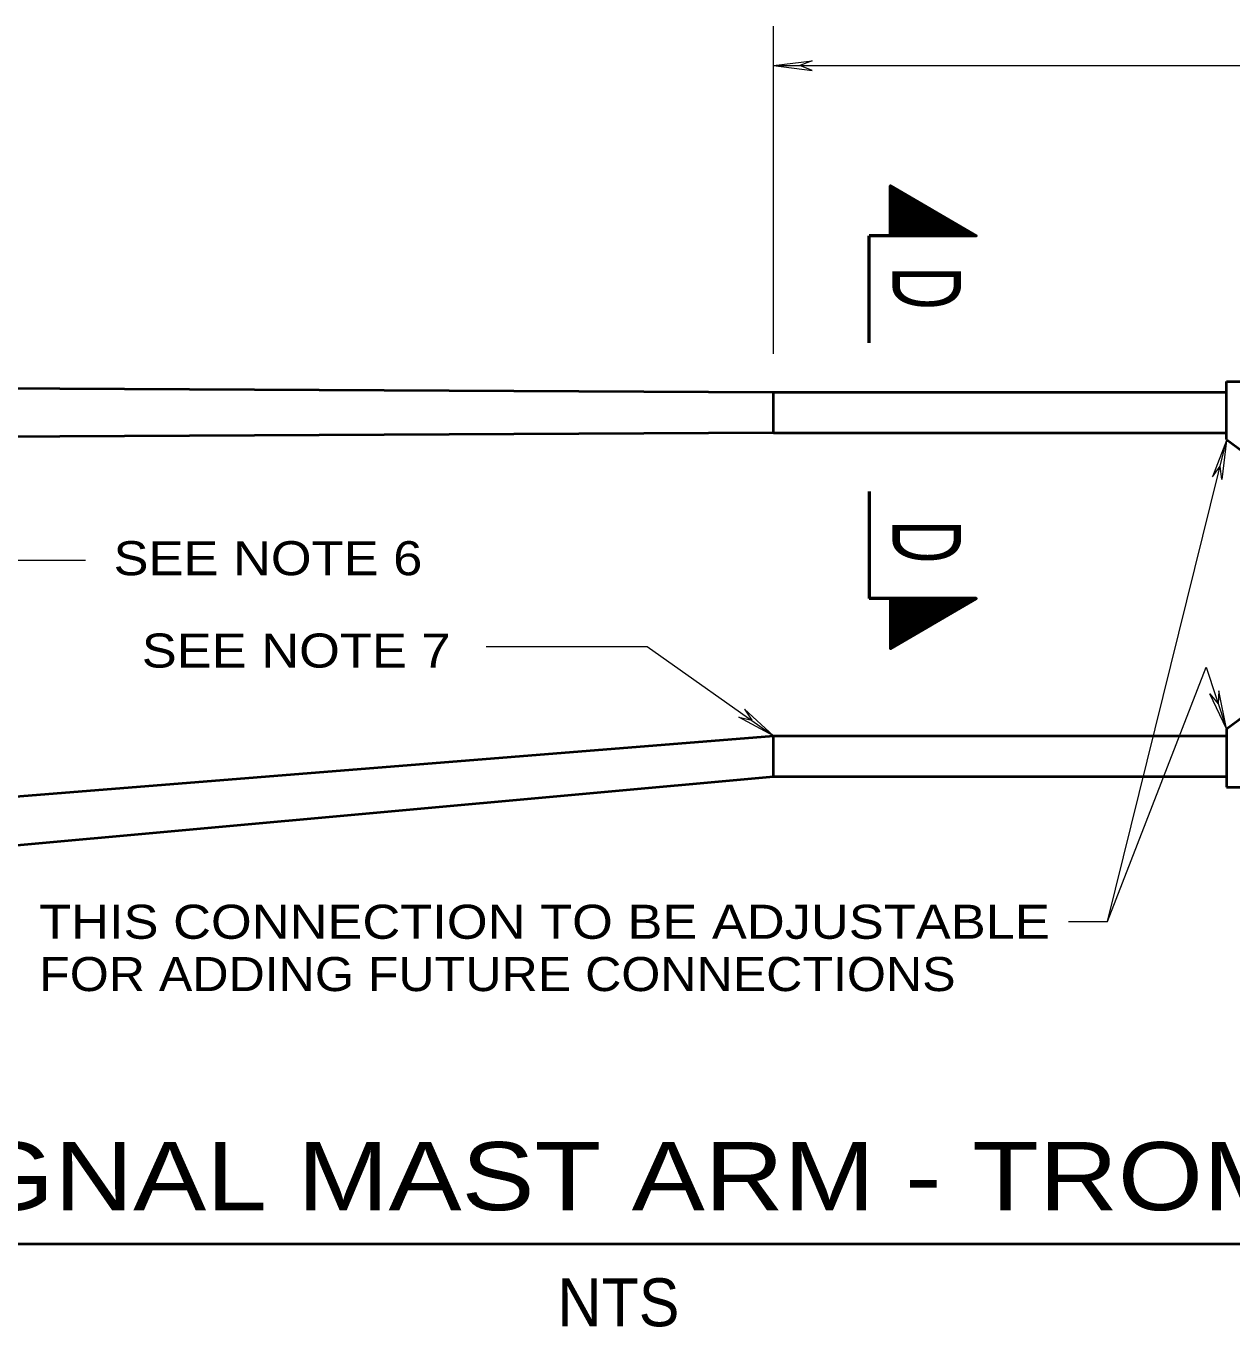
# Model space of a CAD drawing. Extents: x 312583 to 312854, y 144419 to 144597.
# Drawn here: x 312774.43 to 312801.32, y 144536.56 to 144565.58 of the extents above; entities that cross this region are included whole.
import ezdxf
from ezdxf.enums import TextEntityAlignment as Align

# ---------------------------------------------------------------- set-up
doc = ezdxf.new("R2010")
doc.units = 0
doc.header["$LTSCALE"] = 0.3
doc.layers.add('1', color=7, linetype='Continuous', lineweight=35)
doc.layers.add('2', color=7, linetype='Continuous', lineweight=13)

msp = doc.modelspace()

# ---------------------------------------------------------------- linework, layer by layer
at = {"layer": '1'}
for p, q in [((312793.7022, 144561.9803), (312793.7176, 144561.9956)), ((312793.7022, 144561.9343), (312793.7406, 144561.9879)), ((312793.7022, 144561.8806), (312793.7559, 144561.9726)), ((312793.7022, 144561.8346), (312793.7789, 144561.9573)), ((312793.7022, 144561.7809), (312793.8019, 144561.9496)), ((312793.7022, 144561.7426), (312793.8172, 144561.9343)), ((312793.7022, 144561.6889), (312793.8402, 144561.9266)), ((312793.7022, 144561.6429), (312793.8632, 144561.9113)), ((312793.7022, 144561.5969), (312793.8786, 144561.9036)), ((312793.7022, 144561.5509), (312793.9092, 144561.8883)), ((312793.7022, 144561.4973), (312793.9246, 144561.8806)), ((312793.7022, 144561.4513), (312793.9476, 144561.8653)), ((312793.7022, 144561.4053), (312793.9706, 144561.8576)), ((312793.7022, 144561.3516), (312793.9859, 144561.8423)), ((312793.7022, 144561.3056), (312794.0089, 144561.8346)), ((312793.7022, 144561.2596), (312794.0242, 144561.8193)), ((312793.7022, 144561.2059), (312794.0472, 144561.8039)), ((312793.7022, 144561.1599), (312794.0702, 144561.7963)), ((312793.7022, 144561.1139), (312794.0856, 144561.7809)), ((312793.7022, 144561.0679), (312794.1086, 144561.7656)), ((312793.7022, 144561.0143), (312794.1316, 144561.7579)), ((312793.7022, 144560.9759), (312794.1469, 144561.7426)), ((312793.7022, 144560.9223), (312794.1776, 144561.7349)), ((312793.7176, 144560.8993), (312794.1929, 144561.7196)), ((312793.7482, 144560.8993), (312794.2159, 144561.7119)), ((312793.7789, 144560.8993), (312794.2389, 144561.6966)), ((312793.8019, 144560.8993), (312794.2542, 144561.6889)), ((312793.8326, 144560.8993), (312794.2772, 144561.6736)), ((312793.8556, 144560.9069), (312794.3002, 144561.6659)), ((312793.8862, 144560.9069), (312794.3156, 144561.6506)), ((312793.9092, 144560.8993), (312794.3386, 144561.6429)), ((312793.9399, 144560.8993), (312794.3616, 144561.6276)), ((312793.9706, 144560.8993), (312794.3769, 144561.6123)), ((312793.9936, 144560.8993), (312794.3999, 144561.6046)), ((312794.0242, 144560.8993), (312794.4229, 144561.5893)), ((312794.0549, 144560.8993), (312794.4459, 144561.5739)), ((312794.0779, 144560.8993), (312794.4612, 144561.5663)), ((312794.1086, 144560.9069), (312794.4842, 144561.5509)), ((312794.1392, 144560.8993), (312794.5072, 144561.5433)), ((312794.1622, 144560.8993), (312794.5226, 144561.5279)), ((312794.1852, 144560.8993), (312794.5456, 144561.5203)), ((312794.2159, 144560.8993), (312794.5686, 144561.5049)), ((312794.2466, 144560.8993), (312794.5839, 144561.4973)), ((312794.2772, 144560.8993), (312794.6069, 144561.4819)), ((312794.3002, 144560.8993), (312794.6299, 144561.4743)), ((312794.3309, 144560.8993), (312794.6452, 144561.4589)), ((312794.3539, 144560.9069), (312794.6759, 144561.4513)), ((312794.3846, 144560.8993), (312794.6912, 144561.4359)), ((312794.4076, 144560.8993), (312794.7142, 144561.4206)), ((312794.4382, 144560.8993), (312794.7372, 144561.4129)), ((312794.4689, 144560.8993), (312794.7526, 144561.3976)), ((312794.4919, 144560.8993), (312794.7756, 144561.3899)), ((312794.5226, 144560.8993), (312794.7986, 144561.3746)), ((312794.5532, 144560.8993), (312794.8139, 144561.3669)), ((312794.5762, 144560.8993), (312794.8369, 144561.3516)), ((312794.6069, 144560.8993), (312794.8599, 144561.3439)), ((312794.6376, 144560.8993), (312794.8752, 144561.3286)), ((312794.6606, 144560.8993), (312794.8982, 144561.3209)), ((312794.6836, 144560.8993), (312794.9212, 144561.3056)), ((312794.7142, 144560.8993), (312794.9442, 144561.2979)), ((312794.7449, 144560.8993), (312794.9596, 144561.2826)), ((312794.7756, 144560.8993), (312794.9826, 144561.2673)), ((312794.7986, 144560.8993), (312795.0056, 144561.2596)), ((312794.8292, 144560.8993), (312795.0209, 144561.2443)), ((312794.8522, 144560.8993), (312795.0439, 144561.2289)), ((312794.8829, 144560.8993), (312795.0669, 144561.2213)), ((312794.9059, 144560.8993), (312795.0822, 144561.2059)), ((312794.9366, 144560.8993), (312795.1052, 144561.1983)), ((312794.9672, 144560.8993), (312795.1282, 144561.1829)), ((312794.9902, 144560.8993), (312795.1436, 144561.1753)), ((312795.0209, 144560.8993), (312795.1742, 144561.1599)), ((312795.0439, 144560.8993), (312795.1896, 144561.1523)), ((312795.0746, 144560.8993), (312795.2126, 144561.1369)), ((312795.1052, 144560.8993), (312795.2356, 144561.1293)), ((312795.1282, 144560.8993), (312795.2509, 144561.1139)), ((312795.1589, 144560.8993), (312795.2739, 144561.1063)), ((312795.1819, 144560.8993), (312795.2969, 144561.0909)), ((312795.2126, 144560.8993), (312795.3122, 144561.0756)), ((312795.2432, 144560.8993), (312795.3352, 144561.0679)), ((312795.2739, 144560.8993), (312795.3582, 144561.0526)), ((312795.2969, 144560.8993), (312795.3736, 144561.0373)), ((312795.3276, 144560.8993), (312795.3966, 144561.0296)), ((312795.3506, 144560.8993), (312795.4196, 144561.0143)), ((312795.3736, 144560.8993), (312795.4426, 144561.0066)), ((312795.4042, 144560.8993), (312795.4579, 144560.9913)), ((312795.4349, 144560.8993), (312795.4809, 144560.9836)), ((312795.4656, 144560.8993), (312795.5039, 144560.9683)), ((312795.4886, 144560.8993), (312795.5192, 144560.9606)), ((312795.5192, 144560.8993), (312795.5422, 144560.9453)), ((312795.5422, 144560.8993), (312795.5652, 144560.9376)), ((312795.5729, 144560.8993), (312795.5806, 144560.9223)), ((312795.6036, 144560.8993), (312795.6036, 144560.9146)), ((312793.7022, 144552.7803), (312794.1776, 144551.9676)), ((312793.7022, 144552.7266), (312794.1469, 144551.9599)), ((312793.7022, 144552.6883), (312794.1316, 144551.9446)), ((312793.7176, 144552.8033), (312794.1929, 144551.9829)), ((312793.7482, 144552.8033), (312794.2159, 144551.9906)), ((312793.7789, 144552.8033), (312794.2389, 144552.0059)), ((312793.8019, 144552.8033), (312794.2542, 144552.0136)), ((312793.8326, 144552.8033), (312794.2772, 144552.0289)), ((312793.8556, 144552.7956), (312794.3002, 144552.0366)), ((312793.8862, 144552.7956), (312794.3156, 144552.0519)), ((312793.9092, 144552.8033), (312794.3386, 144552.0596)), ((312793.9399, 144552.8033), (312794.3616, 144552.0749)), ((312793.9706, 144552.8033), (312794.3769, 144552.0903)), ((312793.9936, 144552.8033), (312794.3999, 144552.0979)), ((312794.0242, 144552.8033), (312794.4229, 144552.1133)), ((312794.0549, 144552.8033), (312794.4459, 144552.1286)), ((312794.0779, 144552.8033), (312794.4612, 144552.1363)), ((312794.1086, 144552.7956), (312794.4842, 144552.1516)), ((312794.1392, 144552.8033), (312794.5072, 144552.1593)), ((312794.1622, 144552.8033), (312794.5226, 144552.1746)), ((312794.1852, 144552.8033), (312794.5456, 144552.1823)), ((312794.2159, 144552.8033), (312794.5686, 144552.1976)), ((312794.2466, 144552.8033), (312794.5839, 144552.2053)), ((312794.2772, 144552.8033), (312794.6069, 144552.2206)), ((312794.3002, 144552.8033), (312794.6299, 144552.2283)), ((312794.3309, 144552.8033), (312794.6452, 144552.2436)), ((312794.3539, 144552.7956), (312794.6759, 144552.2513)), ((312794.3846, 144552.8033), (312794.6912, 144552.2666)), ((312794.4076, 144552.8033), (312794.7142, 144552.2819)), ((312794.4382, 144552.8033), (312794.7372, 144552.2896)), ((312794.4689, 144552.8033), (312794.7526, 144552.3049)), ((312794.4919, 144552.8033), (312794.7756, 144552.3126)), ((312794.5226, 144552.8033), (312794.7986, 144552.3279)), ((312794.5532, 144552.8033), (312794.8139, 144552.3356)), ((312794.5762, 144552.8033), (312794.8369, 144552.3509)), ((312794.6069, 144552.8033), (312794.8599, 144552.3586)), ((312794.6376, 144552.8033), (312794.8752, 144552.3739)), ((312794.6606, 144552.8033), (312794.8982, 144552.3816)), ((312794.6836, 144552.8033), (312794.9212, 144552.3969)), ((312794.7142, 144552.8033), (312794.9442, 144552.4046)), ((312794.7449, 144552.8033), (312794.9596, 144552.4199)), ((312794.7756, 144552.8033), (312794.9826, 144552.4353)), ((312794.7986, 144552.8033), (312795.0056, 144552.4429)), ((312794.8292, 144552.8033), (312795.0209, 144552.4583)), ((312794.8522, 144552.8033), (312795.0439, 144552.4736)), ((312794.8829, 144552.8033), (312795.0669, 144552.4813)), ((312794.9059, 144552.8033), (312795.0822, 144552.4966)), ((312794.9366, 144552.8033), (312795.1052, 144552.5043)), ((312794.9672, 144552.8033), (312795.1282, 144552.5196)), ((312794.9902, 144552.8033), (312795.1436, 144552.5273)), ((312795.0209, 144552.8033), (312795.1742, 144552.5426)), ((312795.0439, 144552.8033), (312795.1896, 144552.5503)), ((312795.0746, 144552.8033), (312795.2126, 144552.5656)), ((312795.1052, 144552.8033), (312795.2356, 144552.5733)), ((312795.1282, 144552.8033), (312795.2509, 144552.5886)), ((312795.1589, 144552.8033), (312795.2739, 144552.5963)), ((312795.1819, 144552.8033), (312795.2969, 144552.6116)), ((312795.2126, 144552.8033), (312795.3122, 144552.6269)), ((312795.2432, 144552.8033), (312795.3352, 144552.6346)), ((312795.2739, 144552.8033), (312795.3582, 144552.6499)), ((312795.2969, 144552.8033), (312795.3736, 144552.6653)), ((312795.3276, 144552.8033), (312795.3966, 144552.6729)), ((312795.3506, 144552.8033), (312795.4196, 144552.6883)), ((312795.3736, 144552.8033), (312795.4426, 144552.6959)), ((312795.4042, 144552.8033), (312795.4579, 144552.7113)), ((312795.4349, 144552.8033), (312795.4809, 144552.7189)), ((312795.4656, 144552.8033), (312795.5039, 144552.7343)), ((312795.4886, 144552.8033), (312795.5192, 144552.7419)), ((312795.5192, 144552.8033), (312795.5422, 144552.7573)), ((312795.5422, 144552.8033), (312795.5652, 144552.7649)), ((312795.5729, 144552.8033), (312795.5806, 144552.7803)), ((312795.6036, 144552.8033), (312795.6036, 144552.7879)), ((312793.7022, 144552.6346), (312794.1086, 144551.9369)), ((312793.7022, 144552.5886), (312794.0856, 144551.9216)), ((312793.7022, 144552.5426), (312794.0702, 144551.9063)), ((312793.7022, 144552.4966), (312794.0472, 144551.8986)), ((312793.7022, 144552.4429), (312794.0242, 144551.8833)), ((312793.7022, 144552.3969), (312794.0089, 144551.8679)), ((312793.7022, 144552.3509), (312793.9859, 144551.8603)), ((312793.7022, 144552.2973), (312793.9706, 144551.8449)), ((312793.7022, 144552.2513), (312793.9476, 144551.8373)), ((312793.7022, 144552.2053), (312793.9246, 144551.8219)), ((312793.7022, 144552.1516), (312793.9092, 144551.8143)), ((312793.7022, 144552.1056), (312793.8786, 144551.7989)), ((312793.7022, 144552.0596), (312793.8632, 144551.7913)), ((312793.7022, 144552.0136), (312793.8402, 144551.7759)), ((312793.7022, 144551.9599), (312793.8172, 144551.7683)), ((312793.7022, 144551.9216), (312793.8019, 144551.7529)), ((312793.7022, 144551.8679), (312793.7789, 144551.7453)), ((312793.7022, 144551.8219), (312793.7559, 144551.7299)), ((312793.7022, 144551.7683), (312793.7406, 144551.7146)), ((312793.7022, 144551.7223), (312793.7176, 144551.7069))]:
    msp.add_line(p, q, dxfattribs=at)
at = {"layer": '1', "lineweight": 53}
for p, q in [((312793.2269, 144558.5073), (312793.2269, 144560.8993)), ((312793.7022, 144560.8993), (312793.2269, 144560.8993)), ((312793.2269, 144555.1953), (312793.2269, 144552.8033)), ((312793.7022, 144552.8033), (312793.2269, 144552.8033))]:
    msp.add_line(p, q, dxfattribs=at)
at = {"layer": '1', "lineweight": 40}
for p, q in [((312712.2132, 144557.8019), (312791.0956, 144557.4109)), ((312801.2002, 144557.6486), (312802.8716, 144557.6486)), ((312801.2002, 144556.3529), (312801.2002, 144557.6486)), ((312791.0956, 144556.4986), (312791.0956, 144557.4109)), ((312791.0956, 144557.4109), (312801.2002, 144557.4109)), ((312791.0956, 144556.4986), (312712.2132, 144556.1076)), ((312791.0956, 144556.4986), (312801.2002, 144556.4986)), ((312801.2002, 144556.3529), (312801.5606, 144556.0846)), ((312801.2002, 144549.8976), (312801.5606, 144550.1659)), ((312801.2002, 144549.8976), (312801.2002, 144548.5943)), ((312712.2132, 144543.4269), (312791.0956, 144549.7443)), ((312791.0956, 144548.8319), (312791.0956, 144549.7443)), ((312791.0956, 144549.7443), (312801.2002, 144549.7443)), ((312712.2209, 144541.6943), (312791.0956, 144548.8319)), ((312791.0956, 144548.8319), (312801.2002, 144548.8319)), ((312801.2002, 144548.5943), (312802.8716, 144548.5943))]:
    msp.add_line(p, q, dxfattribs=at)
at = {"layer": '1', "lineweight": 53}
for points in [[(312793.7022, 144560.8993), (312793.7022, 144562.0109), (312795.6189, 144560.8993)], [(312793.7022, 144552.8033), (312793.7022, 144551.6916), (312795.6189, 144552.8033)]]:
    msp.add_lwpolyline(points, close=True, dxfattribs=at)
at = {"layer": '2'}
for p, q in [((312791.0956, 144558.2619), (312791.0956, 144565.5759)), ((312791.0956, 144564.6943), (312791.9619, 144564.8016)), ((312791.0956, 144564.6943), (312825.5189, 144564.6943)), ((312791.0956, 144564.6943), (312791.9619, 144564.5869)), ((312791.9619, 144564.8016), (312791.6859, 144564.6943)), ((312791.9619, 144564.5869), (312791.6859, 144564.6943)), ((312801.2002, 144556.3299), (312800.8859, 144555.5173)), ((312801.2002, 144556.3299), (312801.0929, 144555.4636)), ((312800.8859, 144555.5173), (312801.0546, 144555.7549)), ((312801.0929, 144555.4636), (312801.0546, 144555.7549)), ((312775.7546, 144553.6543), (312773.2476, 144553.6543)), ((312800.8246, 144550.6796), (312801.0086, 144550.4573)), ((312801.2002, 144549.8976), (312800.8246, 144550.6796)), ((312801.0239, 144550.7486), (312801.0086, 144550.4573)), ((312801.2002, 144549.8976), (312801.0239, 144550.7486)), ((312790.3212, 144550.1583), (312790.6126, 144550.0893)), ((312791.0956, 144549.7443), (312790.3212, 144550.1583)), ((312790.4516, 144550.3346), (312790.6126, 144550.0893)), ((312791.0956, 144549.7443), (312790.4516, 144550.3346))]:
    msp.add_line(p, q, dxfattribs=at)
at = {"layer": '2', "lineweight": 40}
msp.add_line((312760.1944, 144538.4129), (312815.3652, 144538.4129), dxfattribs=at)
at = {"layer": '2'}
for points in [[(312797.6736, 144545.6043), (312798.5476, 144545.6043), (312801.2002, 144556.3299)], [(312784.6939, 144551.7376), (312788.2819, 144551.7376), (312791.0956, 144549.7443)], [(312798.5476, 144545.6043), (312800.7402, 144551.2776), (312801.2002, 144549.8976)]]:
    msp.add_lwpolyline(points, dxfattribs=at)

# ---------------------------------------------------------------- texts
at = {"layer": '1', "width": 0.65}
for p in [(312793.7482, 144559.73), (312793.7482, 144554.072)]:
    msp.add_text('D', height=1.533, rotation=270.003, dxfattribs=at).set_placement(p, align=Align.CENTER)
at = {"layer": '2'}
for s, height, width, p in [('SEE NOTE 6', 0.76, 1.15, (312776.3833, 144553.3245)), ('SEE NOTE 7', 0.76, 1.15, (312777.0132, 144551.2644)), ('THIS CONNECTION TO BE ADJUSTABLE', 0.76, 1.15, (312774.7243, 144545.2147)), ('FOR ADDING FUTURE CONNECTIONS', 0.76, 1.1, (312774.7243, 144544.0484)), ('TRAFFIC SIGNAL MAST ARM - TROMBONE TYPE ', 1.52, 1.2, (312759.8843, 144539.1606))]:
    msp.add_text(s, height=height, dxfattribs=dict(at, width=width)).set_placement(p)
at = {"layer": '2', "width": 0.95}
msp.add_text('NTS', height=1.07, dxfattribs=at).set_placement((312787.6405, 144536.5708), align=Align.CENTER)

doc.saveas('drawing.dxf')
